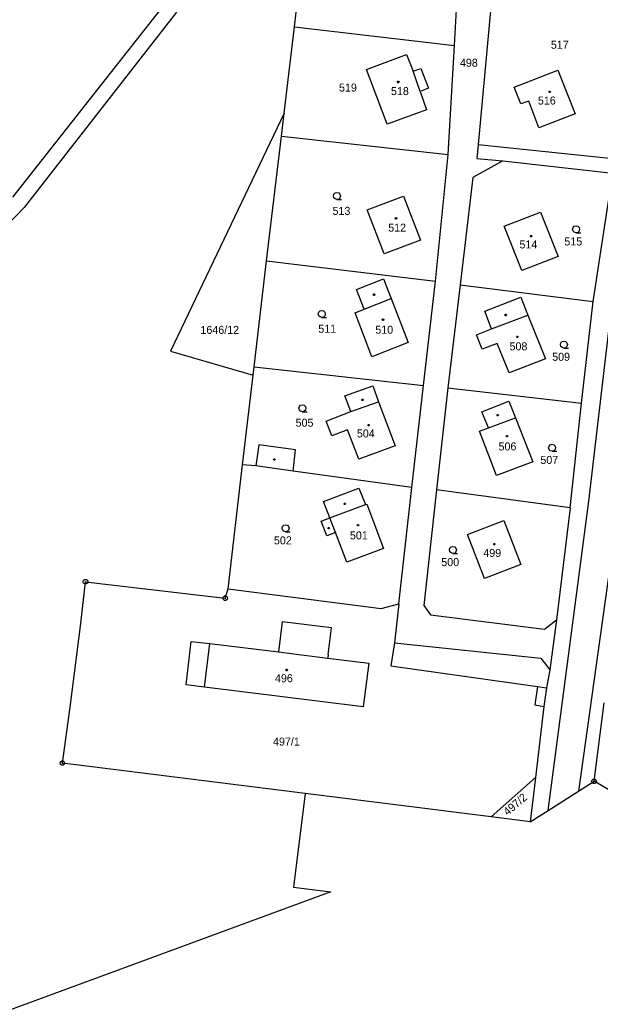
# Model space of a CAD drawing. Extents: x -609861 to -605046, y -1120287 to -1116307.
# Drawn here: x -607503.9 to -607380.6, y -1119963.2 to -1119752.8 of the extents above; entities that cross this region are included whole.
import ezdxf

# ---------------------------------------------------------------- set-up
doc = ezdxf.new("R2010")
doc.units = 0
for name, color, linetype in [('Vrstva 1', 7, 'Continuous'), ('Vrstva 2', 7, 'Continuous'), ('Vrstva 3', 7, 'Continuous'), ('Vrstva 4', 7, 'Continuous'), ('Vrstva 5', 7, 'Continuous'), ('Vrstva 8', 7, 'Continuous')]:
    doc.layers.add(name, color=color, linetype=linetype)

msp = doc.modelspace()

# ---------------------------------------------------------------- linework, layer by layer
at = {"layer": 'Vrstva 1'}
for p, q in [((-607445.53, -1119754.29), (-607443.05, -1119731.17)), ((-607411.55, -1119758.21), (-607410.22, -1119735.13)), ((-607505.44, -1119790.45), (-607472.82, -1119749.13)), ((-607403.73, -1119749.33), (-607406.5, -1119779.28)), ((-607470.62, -1119751.13), (-607503.03, -1119792.65)), ((-607447.74, -1119772.62), (-607445.53, -1119754.29)), ((-607445.53, -1119754.29), (-607411.55, -1119758.21)), ((-607412.86, -1119781.37), (-607411.55, -1119758.21)), ((-607430.24, -1119763.33), (-607421.74, -1119760.13)), ((-607421.74, -1119760.13), (-607420.31, -1119763.72)), ((-607425.87, -1119774.96), (-607430.24, -1119763.33)), ((-607420.31, -1119763.72), (-607418.67, -1119763.14)), ((-607418.67, -1119763.14), (-607417.05, -1119767.32)), ((-607398.83, -1119767.06), (-607389.55, -1119763.47)), ((-607389.55, -1119763.47), (-607385.91, -1119772.79)), ((-607417.05, -1119767.32), (-607418.83, -1119768.01)), ((-607397.42, -1119770.61), (-607398.83, -1119767.06)), ((-607418.83, -1119768.01), (-607417.46, -1119771.89)), ((-607417.46, -1119771.89), (-607425.87, -1119774.96)), ((-607395.75, -1119770.07), (-607397.42, -1119770.61)), ((-607393.61, -1119775.7), (-607395.75, -1119770.07)), ((-607447.74, -1119772.62), (-607471.91, -1119823.19)), ((-607448.33, -1119777.48), (-607447.74, -1119772.62)), ((-607385.91, -1119772.79), (-607393.61, -1119775.7)), ((-607451.47, -1119803.98), (-607448.33, -1119777.48)), ((-607448.33, -1119777.48), (-607412.86, -1119781.37)), ((-607406.5, -1119779.28), (-607406.77, -1119782.22)), ((-607415.55, -1119808.3), (-607412.86, -1119781.37)), ((-607406.77, -1119782.22), (-607401.23, -1119782.74)), ((-607401.23, -1119782.74), (-607407.61, -1119786.29)), ((-607401.23, -1119782.74), (-607377.88, -1119785.33)), ((-607407.61, -1119786.29), (-607410.36, -1119809.08)), ((-607382.05, -1119812.64), (-607377.88, -1119785.33)), ((-607430.11, -1119793.13), (-607422.37, -1119790.24)), ((-607422.37, -1119790.24), (-607418.73, -1119799.6)), ((-607503.03, -1119792.65), (-607539.95, -1119830.8)), ((-607426.48, -1119802.52), (-607430.11, -1119793.13)), ((-607401.01, -1119796.63), (-607393.24, -1119793.64)), ((-607393.24, -1119793.64), (-607389.48, -1119803.05)), ((-607397.24, -1119806.07), (-607401.01, -1119796.63)), ((-607418.73, -1119799.6), (-607426.48, -1119802.52)), ((-607389.48, -1119803.05), (-607397.24, -1119806.07)), ((-607454.15, -1119826.52), (-607451.47, -1119803.98)), ((-607451.47, -1119803.98), (-607415.55, -1119808.3)), ((-607418.09, -1119830.45), (-607415.55, -1119808.3)), ((-607410.36, -1119809.08), (-607412.95, -1119830.97)), ((-607410.36, -1119809.08), (-607382.05, -1119812.64)), ((-607430.75, -1119814.27), (-607424.98, -1119811.99)), ((-607424.98, -1119811.99), (-607421.37, -1119821.32)), ((-607384.53, -1119834.22), (-607382.05, -1119812.64)), ((-607432.66, -1119815.01), (-607430.75, -1119814.27)), ((-607429.11, -1119824.37), (-607432.66, -1119815.01)), ((-607403.66, -1119818.46), (-607395.94, -1119815.51)), ((-607395.94, -1119815.51), (-607392.22, -1119824.83)), ((-607406.86, -1119819.72), (-607403.66, -1119818.46)), ((-607405.65, -1119822.78), (-607406.86, -1119819.72)), ((-607421.37, -1119821.32), (-607429.11, -1119824.37)), ((-607402.5, -1119821.53), (-607405.65, -1119822.78)), ((-607399.94, -1119827.81), (-607402.5, -1119821.53)), ((-607471.91, -1119823.19), (-607454.36, -1119828.29)), ((-607454.36, -1119828.29), (-607454.15, -1119826.52)), ((-607454.15, -1119826.52), (-607418.09, -1119830.45)), ((-607392.22, -1119824.83), (-607399.94, -1119827.81)), ((-607456.59, -1119847.31), (-607454.36, -1119828.29)), ((-607420.59, -1119852.11), (-607418.09, -1119830.45)), ((-607412.95, -1119830.97), (-607415.37, -1119852.65)), ((-607412.95, -1119830.97), (-607384.53, -1119834.22)), ((-607433.56, -1119835.97), (-607427.66, -1119833.91)), ((-607427.66, -1119833.91), (-607424.18, -1119843.26)), ((-607405.7, -1119836.06), (-607399.96, -1119833.81)), ((-607399.96, -1119833.81), (-607398.57, -1119837.31)), ((-607386.96, -1119856.48), (-607384.53, -1119834.22)), ((-607438.8, -1119838.02), (-607433.56, -1119835.97)), ((-607404.34, -1119839.44), (-607405.7, -1119836.06)), ((-607437.64, -1119841.19), (-607438.8, -1119838.02)), ((-607398.57, -1119837.31), (-607394.85, -1119846.65)), ((-607434.26, -1119839.9), (-607437.64, -1119841.19)), ((-607431.88, -1119846.14), (-607434.26, -1119839.9)), ((-607406.2, -1119840.15), (-607404.34, -1119839.44)), ((-607402.59, -1119849.57), (-607406.2, -1119840.15)), ((-607424.18, -1119843.26), (-607431.88, -1119846.14)), ((-607459.65, -1119873.63), (-607456.59, -1119847.31)), ((-607453.74, -1119847.55), (-607456.59, -1119847.31)), ((-607445.82, -1119848.65), (-607453.74, -1119847.55)), ((-607394.85, -1119846.65), (-607402.59, -1119849.57)), ((-607420.59, -1119852.11), (-607445.82, -1119848.65)), ((-607423.35, -1119876.82), (-607420.59, -1119852.11)), ((-607415.37, -1119852.65), (-607418.08, -1119877.18)), ((-607386.96, -1119856.48), (-607415.37, -1119852.65)), ((-607438.05, -1119858.61), (-607430.47, -1119855.78)), ((-607430.47, -1119855.78), (-607430.19, -1119855.67)), ((-607430.19, -1119855.67), (-607426.63, -1119865.06)), ((-607386.96, -1119856.48), (-607389.88, -1119880.27)), ((-607439.9, -1119859.29), (-607438.05, -1119858.61)), ((-607438.68, -1119862.41), (-607439.9, -1119859.29)), ((-607408.76, -1119862.1), (-607401.08, -1119859.12)), ((-607401.08, -1119859.12), (-607397.46, -1119868.48)), ((-607436.84, -1119861.68), (-607438.68, -1119862.41)), ((-607434.41, -1119868.01), (-607436.84, -1119861.68)), ((-607405.15, -1119871.49), (-607408.76, -1119862.1)), ((-607426.63, -1119865.06), (-607434.41, -1119868.01)), ((-607397.46, -1119868.48), (-607405.15, -1119871.49)), ((-607490.95, -1119881.06), (-607489.97, -1119872.15)), ((-607489.97, -1119872.15), (-607460.26, -1119875.66)), ((-607460.26, -1119875.66), (-607459.65, -1119873.63)), ((-607459.65, -1119873.63), (-607427.14, -1119877.86)), ((-607427.14, -1119877.86), (-607423.35, -1119876.82)), ((-607423.35, -1119876.82), (-607424.32, -1119885.14)), ((-607418.08, -1119877.18), (-607416.64, -1119879.17)), ((-607416.64, -1119879.17), (-607392.37, -1119882.22)), ((-607493.21, -1119898.82), (-607490.95, -1119881.06)), ((-607392.37, -1119882.22), (-607389.88, -1119880.27)), ((-607389.88, -1119880.27), (-607391.3, -1119890.88)), ((-607463.55, -1119885.29), (-607448.94, -1119887.08)), ((-607424.32, -1119885.14), (-607393.19, -1119888.36)), ((-607438.36, -1119887.63), (-607438.45, -1119888.37)), ((-607438.45, -1119888.37), (-607429.75, -1119889.44)), ((-607429.75, -1119889.44), (-607430.92, -1119898.74)), ((-607393.19, -1119888.36), (-607391.3, -1119890.88)), ((-607391.3, -1119890.88), (-607391.95, -1119894.71)), ((-607430.92, -1119898.74), (-607464.65, -1119894.56)), ((-607391.95, -1119894.71), (-607392.56, -1119898.63)), ((-607381.88, -1119914.54), (-607379.75, -1119897.87)), ((-607494.87, -1119910.68), (-607493.21, -1119898.82)), ((-607392.56, -1119898.63), (-607394.35, -1119913.76)), ((-607443.28, -1119917.16), (-607494.87, -1119910.68)), ((-607403.77, -1119922.13), (-607394.35, -1119913.76)), ((-607394.35, -1119913.76), (-607395.46, -1119923.17)), ((-607385.19, -1119916.64), (-607381.88, -1119914.54)), ((-607370.02, -1119921.59), (-607381.88, -1119914.54)), ((-607443.28, -1119917.16), (-607445.77, -1119937.01)), ((-607403.77, -1119922.13), (-607443.28, -1119917.16)), ((-607391.63, -1119920.74), (-607385.19, -1119916.64)), ((-607395.46, -1119923.17), (-607391.63, -1119920.74)), ((-607395.46, -1119923.17), (-607403.77, -1119922.13)), ((-607437.83, -1119938), (-607506.11, -1119963.17)), ((-607445.77, -1119937.01), (-607437.83, -1119938))]:
    msp.add_line(p, q, dxfattribs=at)
for points in [[(-607438.36, -1119887.63), (-607437.66, -1119881.96), (-607448.15, -1119880.67), (-607448.94, -1119887.08)], [(-607464.65, -1119894.56), (-607468.59, -1119894.09), (-607467.49, -1119884.82), (-607463.55, -1119885.29)]]:
    msp.add_lwpolyline(points, dxfattribs=at)
at = {"layer": 'Vrstva 3'}
for points in [[(-607436.51, -1119790.95), (-607436.89, -1119790.85), (-607437.16, -1119790.58), (-607437.26, -1119790.21), (-607437.16, -1119789.84), (-607436.89, -1119789.57), (-607436.52, -1119789.47), (-607436.15, -1119789.57), (-607435.88, -1119789.84), (-607435.78, -1119790.22), (-607435.88, -1119790.6), (-607436.15, -1119790.87), (-607436.53, -1119790.97), (-607435.53, -1119790.97)], [(-607385.69, -1119798.02), (-607386.07, -1119797.92), (-607386.34, -1119797.65), (-607386.44, -1119797.28), (-607386.34, -1119796.91), (-607386.07, -1119796.64), (-607385.7, -1119796.54), (-607385.33, -1119796.64), (-607385.06, -1119796.91), (-607384.96, -1119797.29), (-607385.06, -1119797.67), (-607385.33, -1119797.94), (-607385.71, -1119798.04), (-607384.71, -1119798.04)], [(-607439.74, -1119816.01), (-607440.12, -1119815.91), (-607440.39, -1119815.64), (-607440.49, -1119815.27), (-607440.39, -1119814.9), (-607440.12, -1119814.63), (-607439.75, -1119814.53), (-607439.38, -1119814.63), (-607439.11, -1119814.9), (-607439.01, -1119815.28), (-607439.11, -1119815.66), (-607439.38, -1119815.93), (-607439.76, -1119816.03), (-607438.76, -1119816.03)], [(-607388.28, -1119822.52), (-607388.66, -1119822.42), (-607388.93, -1119822.15), (-607389.03, -1119821.78), (-607388.93, -1119821.41), (-607388.66, -1119821.14), (-607388.29, -1119821.04), (-607387.92, -1119821.14), (-607387.65, -1119821.41), (-607387.55, -1119821.79), (-607387.65, -1119822.17), (-607387.92, -1119822.44), (-607388.3, -1119822.54), (-607387.3, -1119822.54)], [(-607443.86, -1119836.03), (-607444.24, -1119835.93), (-607444.51, -1119835.66), (-607444.61, -1119835.29), (-607444.51, -1119834.92), (-607444.24, -1119834.65), (-607443.87, -1119834.55), (-607443.5, -1119834.65), (-607443.23, -1119834.92), (-607443.13, -1119835.3), (-607443.23, -1119835.68), (-607443.5, -1119835.95), (-607443.88, -1119836.05), (-607442.88, -1119836.05)], [(-607390.79, -1119844.43), (-607391.17, -1119844.33), (-607391.44, -1119844.06), (-607391.54, -1119843.69), (-607391.44, -1119843.32), (-607391.17, -1119843.05), (-607390.8, -1119842.95), (-607390.43, -1119843.05), (-607390.16, -1119843.32), (-607390.06, -1119843.7), (-607390.16, -1119844.08), (-607390.43, -1119844.35), (-607390.81, -1119844.45), (-607389.81, -1119844.45)], [(-607447.42, -1119861.52), (-607447.8, -1119861.42), (-607448.07, -1119861.15), (-607448.17, -1119860.78), (-607448.07, -1119860.41), (-607447.8, -1119860.14), (-607447.43, -1119860.04), (-607447.06, -1119860.14), (-607446.79, -1119860.41), (-607446.69, -1119860.79), (-607446.79, -1119861.17), (-607447.06, -1119861.44), (-607447.44, -1119861.54), (-607446.44, -1119861.54)], [(-607411.85, -1119866.14), (-607412.23, -1119866.04), (-607412.5, -1119865.77), (-607412.6, -1119865.4), (-607412.5, -1119865.03), (-607412.23, -1119864.76), (-607411.86, -1119864.66), (-607411.49, -1119864.76), (-607411.22, -1119865.03), (-607411.12, -1119865.41), (-607411.22, -1119865.79), (-607411.49, -1119866.06), (-607411.87, -1119866.16), (-607410.87, -1119866.16)]]:
    msp.add_lwpolyline(points, dxfattribs=at)
at = {"layer": 'Vrstva 4'}
for p, q in [((-607418.83, -1119768.01), (-607420.31, -1119763.72)), ((-607406.5, -1119779.28), (-607377.88, -1119782.23)), ((-607382.96, -1119855.04), (-607374.82, -1119785.16)), ((-607432.4, -1119810.04), (-607426.61, -1119807.79)), ((-607426.61, -1119807.79), (-607424.98, -1119811.99)), ((-607430.75, -1119814.27), (-607432.4, -1119810.04)), ((-607405.06, -1119814.68), (-607397.46, -1119811.72)), ((-607397.46, -1119811.72), (-607395.94, -1119815.51)), ((-607403.66, -1119818.46), (-607405.06, -1119814.68)), ((-607434.85, -1119832.64), (-607428.92, -1119830.54)), ((-607428.92, -1119830.54), (-607427.66, -1119833.91)), ((-607433.56, -1119835.97), (-607434.85, -1119832.64)), ((-607404.34, -1119839.44), (-607398.57, -1119837.31)), ((-607453.13, -1119843.09), (-607453.74, -1119847.55)), ((-607445.33, -1119844.13), (-607453.13, -1119843.09)), ((-607445.82, -1119848.65), (-607445.33, -1119844.13)), ((-607439.39, -1119855.08), (-607431.86, -1119852.27)), ((-607431.86, -1119852.27), (-607430.47, -1119855.78)), ((-607376.24, -1119852.84), (-607385.19, -1119916.64)), ((-607438.05, -1119858.61), (-607439.39, -1119855.08)), ((-607391.63, -1119920.74), (-607382.96, -1119855.04)), ((-607436.84, -1119861.68), (-607438.05, -1119858.61)), ((-607464.65, -1119894.56), (-607463.55, -1119885.29)), ((-607424.32, -1119885.14), (-607425.08, -1119889.99)), ((-607448.94, -1119887.08), (-607444.06, -1119887.67)), ((-607444.06, -1119887.67), (-607438.45, -1119888.37)), ((-607425.08, -1119889.99), (-607393.9, -1119894.41)), ((-607393.9, -1119894.41), (-607394.47, -1119898.33)), ((-607393.9, -1119894.41), (-607391.95, -1119894.71)), ((-607394.47, -1119898.33), (-607392.56, -1119898.63))]:
    msp.add_line(p, q, dxfattribs=at)
at = {"layer": 'Vrstva 5'}
for points in [[(-607423.42, -1119765.85), (-607423.33, -1119766), (-607423.42, -1119766.15), (-607423.6, -1119766.15), (-607423.69, -1119766), (-607423.6, -1119765.85)], [(-607391.2, -1119767.95), (-607391.11, -1119768.1), (-607391.2, -1119768.25), (-607391.38, -1119768.25), (-607391.47, -1119768.1), (-607391.38, -1119767.95)], [(-607423.89, -1119794.8), (-607423.8, -1119794.95), (-607423.89, -1119795.1), (-607424.07, -1119795.1), (-607424.16, -1119794.95), (-607424.07, -1119794.8)], [(-607395.15, -1119798.6), (-607395.06, -1119798.75), (-607395.15, -1119798.9), (-607395.33, -1119798.9), (-607395.42, -1119798.75), (-607395.33, -1119798.6)], [(-607428.53, -1119811.03), (-607428.44, -1119811.18), (-607428.53, -1119811.33), (-607428.71, -1119811.33), (-607428.8, -1119811.18), (-607428.71, -1119811.03)], [(-607400.56, -1119815.35), (-607400.47, -1119815.5), (-607400.56, -1119815.65), (-607400.74, -1119815.65), (-607400.83, -1119815.5), (-607400.74, -1119815.35)], [(-607426.66, -1119816.33), (-607426.57, -1119816.48), (-607426.66, -1119816.63), (-607426.84, -1119816.63), (-607426.93, -1119816.48), (-607426.84, -1119816.33)], [(-607398.06, -1119819.97), (-607397.97, -1119820.12), (-607398.06, -1119820.27), (-607398.24, -1119820.27), (-607398.33, -1119820.12), (-607398.24, -1119819.97)], [(-607431, -1119833.35), (-607430.91, -1119833.5), (-607431, -1119833.65), (-607431.18, -1119833.65), (-607431.27, -1119833.5), (-607431.18, -1119833.35)], [(-607402.26, -1119836.61), (-607402.17, -1119836.76), (-607402.26, -1119836.91), (-607402.44, -1119836.91), (-607402.53, -1119836.76), (-607402.44, -1119836.61)], [(-607429.7, -1119838.75), (-607429.61, -1119838.9), (-607429.7, -1119839.05), (-607429.88, -1119839.05), (-607429.97, -1119838.9), (-607429.88, -1119838.75)], [(-607400.28, -1119841.07), (-607400.19, -1119841.22), (-607400.28, -1119841.37), (-607400.46, -1119841.37), (-607400.55, -1119841.22), (-607400.46, -1119841.07)], [(-607449.74, -1119846.06), (-607449.65, -1119846.21), (-607449.74, -1119846.36), (-607449.92, -1119846.36), (-607450.01, -1119846.21), (-607449.92, -1119846.06)], [(-607434.76, -1119855.47), (-607434.67, -1119855.62), (-607434.76, -1119855.77), (-607434.94, -1119855.77), (-607435.03, -1119855.62), (-607434.94, -1119855.47)], [(-607431.94, -1119859.98), (-607431.85, -1119860.13), (-607431.94, -1119860.28), (-607432.12, -1119860.28), (-607432.21, -1119860.13), (-607432.12, -1119859.98)], [(-607438.2, -1119860.64), (-607438.11, -1119860.79), (-607438.2, -1119860.94), (-607438.38, -1119860.94), (-607438.47, -1119860.79), (-607438.38, -1119860.64)], [(-607403.01, -1119864.04), (-607402.92, -1119864.19), (-607403.01, -1119864.34), (-607403.19, -1119864.34), (-607403.28, -1119864.19), (-607403.19, -1119864.04)], [(-607447.12, -1119890.75), (-607447.03, -1119890.9), (-607447.12, -1119891.05), (-607447.3, -1119891.05), (-607447.39, -1119890.9), (-607447.3, -1119890.75)]]:
    msp.add_lwpolyline(points, close=True, dxfattribs=at)
at = {"layer": 'Vrstva 8'}
for p, q in [((-607490.09, -1119872.15), (-607489.85, -1119872.15)), ((-607460.38, -1119875.66), (-607460.14, -1119875.66)), ((-607494.99, -1119910.68), (-607494.75, -1119910.68)), ((-607382, -1119914.54), (-607381.76, -1119914.54))]:
    msp.add_line(p, q, dxfattribs=at)
for points in [[(-607489.82, -1119871.67), (-607489.57, -1119871.85), (-607489.47, -1119872.14), (-607489.57, -1119872.43), (-607489.82, -1119872.61), (-607490.13, -1119872.61), (-607490.38, -1119872.43), (-607490.48, -1119872.14), (-607490.38, -1119871.85), (-607490.13, -1119871.67)], [(-607460.11, -1119875.18), (-607459.86, -1119875.36), (-607459.76, -1119875.65), (-607459.86, -1119875.94), (-607460.11, -1119876.12), (-607460.42, -1119876.12), (-607460.67, -1119875.94), (-607460.77, -1119875.65), (-607460.67, -1119875.36), (-607460.42, -1119875.18)], [(-607494.72, -1119910.2), (-607494.47, -1119910.38), (-607494.37, -1119910.67), (-607494.47, -1119910.96), (-607494.72, -1119911.14), (-607495.03, -1119911.14), (-607495.28, -1119910.96), (-607495.38, -1119910.67), (-607495.28, -1119910.38), (-607495.03, -1119910.2)], [(-607381.73, -1119914.06), (-607381.48, -1119914.24), (-607381.38, -1119914.53), (-607381.48, -1119914.82), (-607381.73, -1119915), (-607382.04, -1119915), (-607382.29, -1119914.82), (-607382.39, -1119914.53), (-607382.29, -1119914.24), (-607382.04, -1119914.06)]]:
    msp.add_lwpolyline(points, close=True, dxfattribs=at)

# ---------------------------------------------------------------- texts
at = {"layer": 'Vrstva 2'}
for s, p in [('517', (-607391.053, -1119758.93)), ('498', (-607410.383, -1119762.76)), ('519', (-607436.083, -1119768.03)), ('518', (-607425.033, -1119768.78)), ('516', (-607393.813, -1119770.78)), ('513', (-607437.463, -1119794.22)), ('512', (-607425.623, -1119797.79)), ('515', (-607388.183, -1119800.72)), ('514', (-607397.733, -1119801.35)), ('1646/12', (-607465.537, -1119819.5)), ('511', (-607440.493, -1119819.26)), ('510', (-607428.363, -1119819.47)), ('508', (-607399.843, -1119823)), ('509', (-607390.773, -1119825.22)), ('505', (-607445.313, -1119839.22)), ('504', (-607432.283, -1119841.5)), ('506', (-607402.173, -1119844.26)), ('507', (-607393.283, -1119847.13)), ('502', (-607449.913, -1119864.22)), ('501', (-607433.763, -1119863.16)), ('499', (-607405.413, -1119866.89)), ('500', (-607414.343, -1119868.84)), ('496', (-607449.703, -1119893.5)), ('497/1', (-607450.113, -1119906.96))]:
    msp.add_text(s, height=1.7, dxfattribs=at).set_placement(p)
msp.add_text('497/2', height=1.7, rotation=40.50812, dxfattribs=at).set_placement((-607400.259, -1119921.936))

doc.saveas('drawing.dxf')
